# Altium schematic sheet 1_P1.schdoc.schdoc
size 220 x 160 mm; Symbol: Sheet-Symbol_A4; Device: Sheet-Symbol_A4; @Project Name: oven_danger; @Page Count: 1; @Update Date: 2024-05-19; @Create Date: 2024-05-19; @Schematic Name: Schematic1; @Page No: 1; @Page Name: P1; Company: EasyEDA.com; Reviewed: EasyEDA; Version: V0.1; Page Size: A4; Part Number: JLCPCB-002; Drawn: EasyEDA
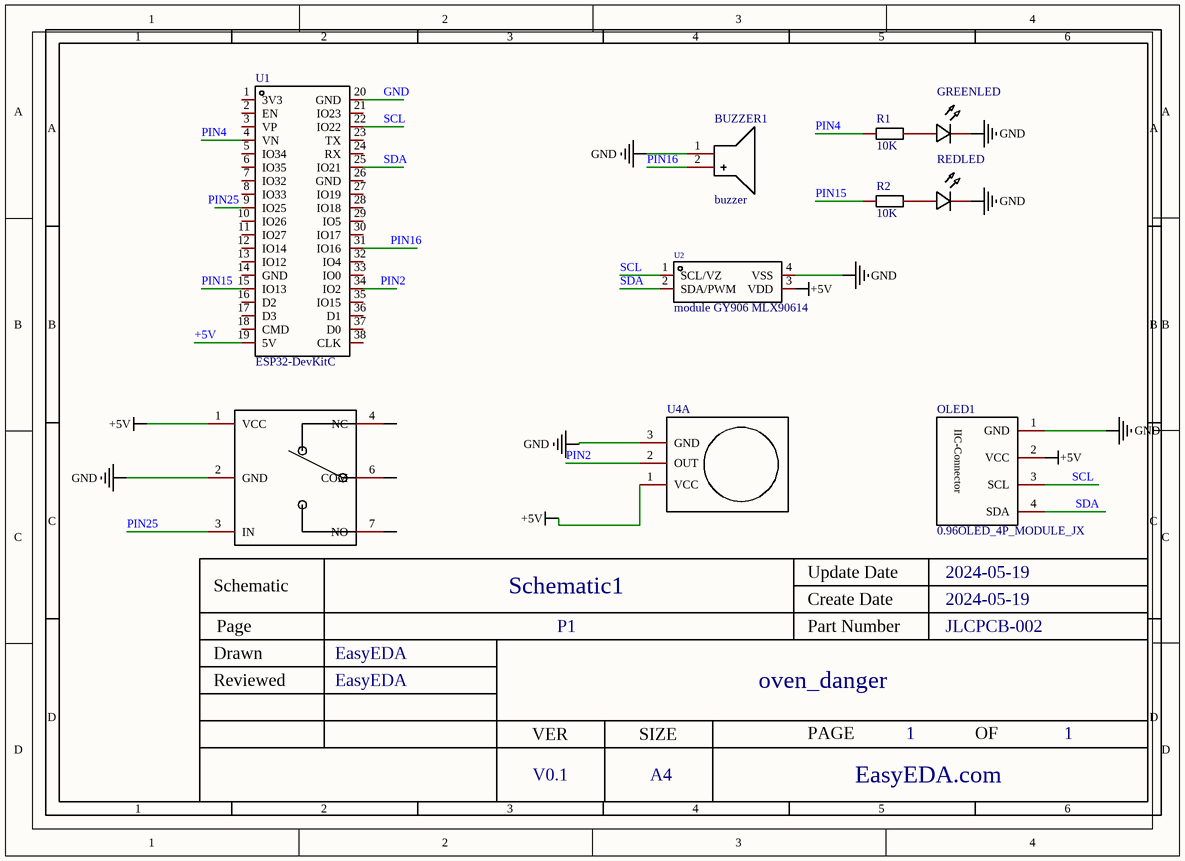
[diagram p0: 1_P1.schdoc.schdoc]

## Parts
?  Relay-CAMM-v2  (value not drawn)
BUZZER1  buzzer  [BUZ-TH_BD12.0-P6.00-D0.9-RD]
GREENLED  LED_0402-R  [LED0402-RD_YELLOW]  (value not drawn)
OLED1  0.96OLED_4P_MODULE_JX  [0.96OLED_4P]
R1  10K  [R0201]
R2  10K  [R0201]
REDLED  LED_0402-R  [LED0402-RD_YELLOW]  (value not drawn)
U1  ESP32-DevKitC  [BULETM-SMD_ESP32-DEVKITC]
U2  module GY906 MLX90614  [TO-39-4_MELEXIS_MLX90614XXA]
U4  HC-SR501  (value not drawn)  (part A of 2)

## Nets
+5V: ?.1(VCC) OLED1.2(VCC) U1.19(5V) U2.3(VDD) U4.1(VCC)
GND: ?.2(GND) BUZZER1.1(-) GREENLED.2(C) OLED1.1(GND) REDLED.2(C) U1.20(GND) U2.4(VSS) U4.3(GND)
PIN2: U1.34(IO2) U4.2(OUT)
PIN4: R1.1 U1.4(VN)
PIN15: R2.1 U1.15(IO13)
PIN16: BUZZER1.2(+) U1.31(IO16)
PIN25: ?.3(IN)
SCL: OLED1.3(SCL) U1.22(IO22) U2.1(SCL/VZ)
SDA: OLED1.4(SDA) U1.25(IO21) U2.2(SDA/PWM)
NetGREENLED_1: GREENLED.1(A) R1.2
NetR2_2: R2.2 REDLED.1(A)

Not connected (* = marked no-connect by the designer): ? 4(NC) 6(COM) 7(NO); U1 1(3V3) 2(EN) 3(VP) 5(IO34) 6(IO35) 7(IO32) 8(IO33) 9(IO25) 10(IO26) 11(IO27) 12(IO14) 13(IO12) 14(GND) 16(D2) 17(D3) 18(CMD) 21(IO23) 23(TX) 24(RX) 26(GND) 27(IO19) 28(IO18) 29(IO5) 30(IO17) 32(IO4) 33(IO0) 35(IO15) 36(D1) 37(D0) 38(CLK)

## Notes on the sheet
- Labels drawn without touching a wire or pin: PIN25

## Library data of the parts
BUZZER1 = buzzer: Add into BOM: yes
GREENLED REDLED = LED_0402-R: Symbol: LED_R; Convert to PCB: yes
OLED1 = 0.96OLED_4P_MODULE_JX: Add into BOM: yes
R1 R2 = Res_0201: Symbol: Res; Convert to PCB: yes
U1 = ESP32-DevKitC: Manufacturer: ESPRESSIF(乐鑫); Add into BOM: yes; Description: CPU:- ROM Size:- Number of I/O: USB:- WIFI Protocols:- Bluetooth:- Ethernet:- Audio & Video Interface:- Multimedia Support:- Card Type:- Power Supply Type:- Power Supply:- POE Support:- Resolution:- Temperature Range:-
U2 = MLX90614ESF-BBA-000-TU: Manufacturer: Melexis(比利时迈来芯); Add into BOM: yes; Supply Voltage: 2.6V~3.6V; Description: Resolution:- Resolution:- Supply Voltage:2.6V~3.6V Supply Voltage:2.6V~3.6V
